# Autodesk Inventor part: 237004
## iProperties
Created: 2006-08
Part Number: 237004
Material: FSt vz
Description: Federring
Vendor: Autodesk Inc.
Document SubType Name: Modeling
Standard: DIN 127
Designer: I.Baliuc
Standards Organization: DIN
Language: de-DE
Size Designation: A 10
Categories: <MemberInstance Version="R10.0.0"><Categories><Category DisplayName="Schrauben" InternalName="e4da775c-781d-43d5-af7c-5136215cf5a6" Mnemonic="FSTN"><Category Di
Density: 7.85 g/cm^3
Mass: 2.83415 g
Surface Area: 5.42291 cm^2
Volume: 0.361038 cm^3
Abmessung: A 10
Author: T.Messerschmitt
Comments: DIN 127 - A 10
Revision Number: 237004
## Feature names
1. Körper [Extrusion]
2. Schnitt [Extrusion]
